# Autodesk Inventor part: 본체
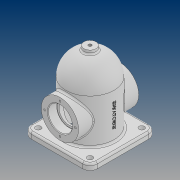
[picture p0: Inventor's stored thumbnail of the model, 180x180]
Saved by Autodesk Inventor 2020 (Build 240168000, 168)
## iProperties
Created: 2021-08
Part Number: 본체
Material: 일반
Document SubType Name: Modeling
Designer: PC312-
Density: 1 g/cm^3
Appearance: 기본값
Mass: 320.706 g
Surface Area: 800.746 cm^2
Volume: 320.706 cm^3
Author: PC312-
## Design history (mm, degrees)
sketch "스케치1"
  geometry: C1 r 40 at (0, 0); 1 further point
  constraints: 1 centre point, 1 coincident
  dimensions: "d0" = 80 diameter of C1
extrude "돌출1" new body sketch "스케치1" distance "d1" = 84; taper "d2" = 0 deg
sketch "스케치3"
  geometry: C1 r 40 at (0, 0) reference; 1 further point
extrude "돌출3" join sketch "스케치3" distance "d7" = 40; taper "d8" = 0 deg
fillet "모깎기1" dims "d9" = 40
feature "쉘1" dims "d10" = 8
sketch "스케치2"
  geometry: L1 (-55, 55)-(55, 55); L2 (55, 55)-(55, -55); L3 (55, -55)-(-55, -55); L4 (-55, -55)-(-55, 55); L5 (-55, 55)-(55, -55); L6 (55, 55)-(-55, -55); 1 further point
  constraints: 12 end point, 2 midpoint, 2 parallel, 1 horizontal, 1 perpendicular
  dimensions: "d3" = 110 distance of L2.end L3.end; "d4" = 110 distance of L1.end L2.end
extrude "돌출2" join sketch "스케치2" distance "d5" = 10; taper "d6" = 0 deg
sketch "스케치5"
  geometry: C1 r 31 at (0, 48); 1 further point
  constraints: 1 centre point, 1 vertical alignment
  dimensions: "d13" = 62 diameter of C1; "d14" = 48 distance of point (0, 0) C1.centre
extrude "돌출5" join sketch "스케치5" stored distance "d15" = 100; taper "d16" = 0 deg
sketch "스케치6"
  geometry: C1 r 20 at (0, 0); C2 r 31 at (0, 0) reference; 1 further point
  constraints: 1 centre point, 1 concentric
  dimensions: "d17" = 40 diameter of C1
extrude "돌출6" cut sketch "스케치6" distance "d18" = 15; taper "d19" = 0 deg
sketch "스케치7"
  geometry: C1 r 20 at (0, 0) reference; A1 r 25.5 centre (0, 0) between (0, 25.5) and (0, -25.5); 3 further points
  constraints: 4 point on circle, 2 horizontal alignment, 2 vertical alignment, 1 centre point, 1 concentric
  dimensions: "d20" = 51 diameter of A1
hole "구멍1" sketch "스케치7" at (0, 25.5), (0, -25.5), (25.5, 0), (-25.5, 0) diameter "d21" = 3.242; stored, may be unused: countersink angle "d25" = 90 deg, drill point angle "d27" = 118 deg; dims "d22" = 8, "d23" = 4, "d24" = 2, "d26" = 10
sketch "스케치8"
  geometry: C1 r 16.5 at (0, 0); C2 r 20 at (0, 0) reference; 1 further point
  constraints: 1 centre point, 1 concentric
  dimensions: "d28" = 33 diameter of C1
extrude "돌출7" cut sketch "스케치8" extent not by distance; stored distance "d29" = 15; taper "d30" = 0 deg
sketch "스케치4"
  geometry: C1 r 32 at (0, 0) reference; 1 further point
extrude "돌출4" cut sketch "스케치4" stored distance "d11" = 144; taper "d12" = 0 deg
node "작업 평면1"
sketch "스케치9"
  geometry: C1 r 10 at (0, 0); 1 further point
  constraints: 1 centre point, 1 coincident
  dimensions: "d32" = 20 diameter of C1
extrude "돌출8" join sketch "스케치9" stored distance "d33" = 10; taper "d34" = 0 deg
sketch "스케치10"
  geometry: 2 further points
  constraints: 1 coincident
hole "구멍2" sketch "스케치10" at (0, 0) diameter "d35" = 5.1881; stored, may be unused: countersink angle "d39" = 90 deg, drill point angle "d41" = 0 deg; dims "d36" = 12, "d37" = 4, "d38" = 2, "d40" = 16
fillet "모깎기2" dims "d42" = 0.3
chamfer "모따기1" distance "d43" = 1; stored, may be unused: second distance "d44" = 2, angle "d45" = 45 deg
node "작업 평면2"
sketch "스케치11"
  geometry: L1 (0, -55)-(0, 55) reference; 3 further points
  constraints: 1 horizontal alignment, 1 midpoint, 1 other
  dimensions: "d47" = 48 distance from line of L1 point (48, 0)
feature "엠보싱1" sketch "스케치11" dims "d1" = 84, "d2" = 0, "d48" = 0.5, "d49" = 0
fillet "모깎기3" dims "d50" = 12
sketch "스케치12"
  geometry: C1 r 4.5 at (-43, 43); A1 r 12 centre (-43, 43) between (-43, 55) and (-55, 43) reference; 1 further point
  constraints: 1 centre point, 1 concentric
  dimensions: "d51" = 9 diameter of C1
extrude "돌출9" cut sketch "스케치12" extent not by distance; stored distance "d52" = 0; taper "d53" = 0 deg
fillet "모깎기4" dims "d57" = 3
node "솔리드1"
mirror "미러1"
pattern_circular "원형 패턴1" dims angle "d55" = 360 deg
feature "A9D066F2-1C7D-4E18-AEED-F7BC21143FA4" dims "d21" = 3.242, "d22" = 8, "d23" = 4, "d24" = 2, "d25" = 90 deg, "d26" = 10, "d27" = 118 deg
other parameters: "d31" = -129, "d46" = 83.75
